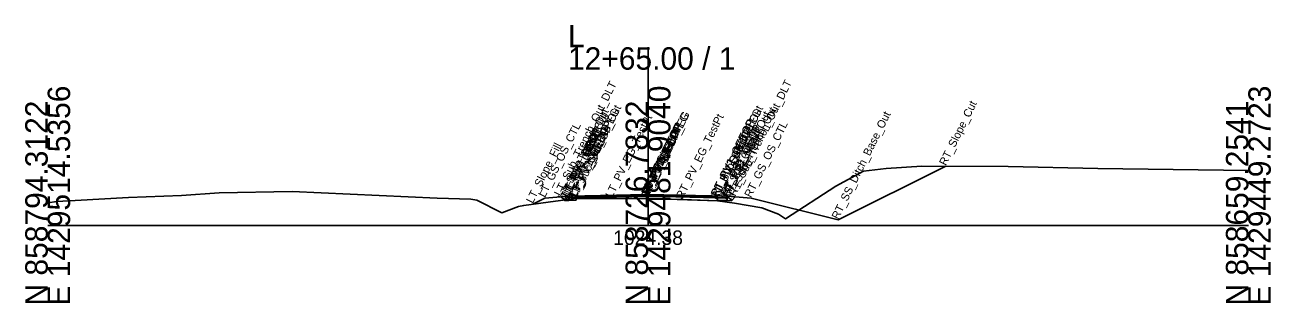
# Model space of a CAD drawing. Extents: x -26 to 2303, y -10 to 19558.
# Drawn here: x 1147.2 to 1302.8, y 3490.3 to 3525.1 of the extents above; entities that cross this region are included whole.
import ezdxf

# ---------------------------------------------------------------- set-up
doc = ezdxf.new("R2010")
doc.units = 0
for name, color, linetype in [('Default', 7, 'Continuous'), ('Exist CMT Pavement', 7, 'Continuous'), ('Exist Cross Section Cell', 7, 'Continuous'), ('Exist XS Center Line Elevation Label', 7, 'Continuous'), ('Exist XS Ground Line', 7, 'Continuous'), ('Prop CMT Conc Surface', 7, 'Continuous'), ('Prop CMT Pvmt Course 1', 7, 'Continuous'), ('Prop CMT Pvmt Course 1 Wedge', 7, 'Continuous'), ('Prop CMT Pvmt Course 2', 7, 'Continuous'), ('Prop CMT Pvmt Course 2 Wedge', 7, 'Continuous'), ('Prop CMT Pvmt Surface', 7, 'Continuous'), ('Prop CMT Pvmt Surface Shoulder', 7, 'Continuous'), ('Prop CMT Pvmt Wedge Surface 1', 7, 'Continuous'), ('Prop CMT Pvmt Wedge Surface 2', 7, 'Continuous'), ('Prop CMT Shld Paved Course 1', 7, 'Continuous'), ('Prop CMT Shld Paved Course 2', 7, 'Continuous'), ('Prop CMT Slope Grass', 7, 'Continuous'), ('Prop CMT Subgrade Earthwork', 7, 'Continuous'), ('Prop XS Dump Level', 7, 'Continuous')]:
    doc.layers.add(name, color=color, linetype=linetype)

msp = doc.modelspace()

# ---------------------------------------------------------------- linework, layer by layer
at = {"layer": 'Exist CMT Pavement'}
for p, q in [((1225, 3503.66), (1216.01, 3503.48)), ((1216.01, 3503.48), (1216.01, 3503.36)), ((1216.01, 3503.36), (1216.03, 3503.36)), ((1216.03, 3503.36), (1220.51, 3503.38)), ((1216.03, 3503.36), (1216.03, 3503.36)), ((1220.51, 3503.38), (1220.51, 3503.38)), ((1220.51, 3503.38), (1220.73, 3503.38)), ((1229.4, 3503.57), (1225, 3503.66)), ((1225, 3503.38), (1225, 3503.38)), ((1225, 3503.38), (1229.08, 3503.25)), ((1229.08, 3503.25), (1229.4, 3503.57))]:
    msp.add_line(p, q, dxfattribs=at)
for points in [[(1225, 3503.38), (1216.01, 3503.36)], [(1216.01, 3503.36), (1220.51, 3503.38)], [(1216.03, 3503.36), (1216.03, 3503.36)], [(1220.51, 3503.38), (1225, 3503.38)], [(1220.73, 3503.38), (1224.74, 3503.39), (1225, 3503.38)], [(1229.34, 3503.24), (1225, 3503.38)], [(1225, 3503.38), (1233.68, 3503.09)], [(1233.68, 3503.09), (1229.34, 3503.24)]]:
    msp.add_lwpolyline(points, dxfattribs=at)
at = {"layer": 'Exist Cross Section Cell'}
for p, q in [((1225, 3500), (1225, 3522.27)), ((1150, 3500), (1225, 3500)), ((1225, 3500), (1300, 3500))]:
    msp.add_line(p, q, dxfattribs=at)
at = {"layer": 'Exist XS Ground Line'}
msp.add_lwpolyline([(1150, 3502.84), (1151.14, 3502.98), (1153.44, 3503.13), (1160.09, 3503.48), (1166.73, 3503.74), (1171.42, 3504.07), (1180.56, 3504.23), (1198.65, 3503.42), (1202.88, 3503.28), (1203.6, 3503.16), (1206.73, 3501.58), (1208.83, 3502.36), (1209.47, 3502.52), (1213.45, 3503.06), (1216.01, 3503.36), (1220.73, 3503.38), (1224.74, 3503.39), (1229.94, 3503.22), (1233.68, 3503.09), (1235.8, 3502.78), (1239.22, 3502.21), (1241.29, 3501.4), (1242.18, 3500.85), (1248.45, 3504.9), (1251.91, 3506.81), (1254.76, 3507.14), (1259.19, 3507.42), (1269.98, 3507.37), (1281.2, 3507.13), (1300, 3506.86)], dxfattribs=at)
at = {"layer": 'Prop CMT Conc Surface'}
msp.add_line((1233.68, 3503.09), (1233.68, 3503.14), dxfattribs=at)
at = {"layer": 'Prop CMT Pvmt Course 1'}
for points in [[(1225, 3503.87), (1215.12, 3503.67)], [(1215.12, 3503.67), (1215.12, 3503.46)], [(1215.12, 3503.46), (1216.01, 3503.48)], [(1216.01, 3503.57), (1225, 3503.75)], [(1216.01, 3503.48), (1216.01, 3503.57)], [(1225, 3503.66), (1225, 3503.87)], [(1225, 3503.87), (1234.87, 3503.65)], [(1225, 3503.66), (1225, 3503.87)], [(1225, 3503.75), (1225, 3503.66), (1225, 3503.66)], [(1233.68, 3503.55), (1225, 3503.75)], [(1225, 3503.75), (1225, 3503.66), (1225, 3503.66)], [(1233.68, 3503.47), (1233.68, 3503.55)], [(1234.87, 3503.44), (1233.68, 3503.47)], [(1234.87, 3503.65), (1234.87, 3503.44)]]:
    msp.add_lwpolyline(points, dxfattribs=at)
at = {"layer": 'Prop CMT Pvmt Course 1 Wedge'}
for points in [[(1225, 3503.75), (1216.01, 3503.57)], [(1225, 3503.75), (1233.68, 3503.55)]]:
    msp.add_lwpolyline(points, dxfattribs=at)
at = {"layer": 'Prop CMT Pvmt Course 2'}
for points in [[(1216.01, 3503.48), (1215.12, 3503.46)], [(1215.12, 3503.46), (1215.12, 3503.13)], [(1215.12, 3503.13), (1216.01, 3503.15)], [(1216.01, 3503.15), (1216.01, 3503.48)], [(1233.68, 3503.14), (1233.68, 3503.47)], [(1233.68, 3503.47), (1234.87, 3503.44)], [(1234.87, 3503.11), (1233.68, 3503.14)], [(1234.87, 3503.44), (1234.87, 3503.11)]]:
    msp.add_lwpolyline(points, dxfattribs=at)
at = {"layer": 'Prop CMT Pvmt Course 2 Wedge'}
for points in [[(1225, 3503.66), (1216.01, 3503.48)], [(1225, 3503.66), (1233.68, 3503.47)]]:
    msp.add_lwpolyline(points, dxfattribs=at)
at = {"layer": 'Prop CMT Pvmt Surface'}
for points in [[(1225, 3503.87), (1215.12, 3503.67)], [(1225, 3503.87), (1234.87, 3503.65)]]:
    msp.add_lwpolyline(points, dxfattribs=at)
at = {"layer": 'Prop CMT Pvmt Surface Shoulder'}
for points in [[(1215.12, 3503.67), (1215.12, 3503.67)], [(1234.87, 3503.65), (1234.87, 3503.65)]]:
    msp.add_lwpolyline(points, dxfattribs=at)
at = {"layer": 'Prop CMT Pvmt Wedge Surface 1'}
for points in [[(1215.12, 3503.46), (1215.12, 3503.67)], [(1216.01, 3503.48), (1215.12, 3503.46)], [(1225, 3503.75), (1216.01, 3503.57)], [(1216.01, 3503.57), (1216.01, 3503.48)], [(1225, 3503.75), (1233.68, 3503.55)], [(1233.68, 3503.55), (1233.68, 3503.47)], [(1233.68, 3503.47), (1234.87, 3503.44)], [(1234.87, 3503.44), (1234.87, 3503.65)]]:
    msp.add_lwpolyline(points, dxfattribs=at)
at = {"layer": 'Prop CMT Pvmt Wedge Surface 2'}
for points in [[(1215.12, 3503.46), (1215.12, 3503.67)], [(1225, 3503.66), (1215.12, 3503.46)], [(1225, 3503.66), (1234.87, 3503.44)], [(1234.87, 3503.44), (1234.87, 3503.65)]]:
    msp.add_lwpolyline(points, dxfattribs=at)
at = {"layer": 'Prop CMT Shld Paved Course 1'}
for points in [[(1215.12, 3503.67), (1214.91, 3503.46)], [(1214.91, 3503.46), (1215.12, 3503.46)], [(1215.12, 3503.67), (1215.12, 3503.67)], [(1215.12, 3503.46), (1215.12, 3503.67)], [(1234.87, 3503.65), (1234.87, 3503.65)], [(1234.87, 3503.65), (1235.09, 3503.44)], [(1234.87, 3503.44), (1234.87, 3503.65)], [(1235.09, 3503.44), (1234.87, 3503.44)]]:
    msp.add_lwpolyline(points, dxfattribs=at)
at = {"layer": 'Prop CMT Shld Paved Course 2'}
for points in [[(1214.91, 3503.46), (1214.57, 3503.12)], [(1214.57, 3503.12), (1215.12, 3503.13)], [(1215.12, 3503.46), (1214.91, 3503.46)], [(1214.91, 3503.46), (1214.91, 3503.46)], [(1215.12, 3503.13), (1215.12, 3503.46)], [(1229.4, 3503.57), (1229.08, 3503.25)], [(1234.87, 3503.44), (1235.09, 3503.44)], [(1234.87, 3503.11), (1234.87, 3503.44)], [(1235.43, 3503.1), (1234.87, 3503.11)], [(1235.09, 3503.44), (1235.09, 3503.44)], [(1235.09, 3503.44), (1235.43, 3503.1)]]:
    msp.add_lwpolyline(points, dxfattribs=at)
at = {"layer": 'Prop CMT Slope Grass'}
for points in [[(1234.87, 3503.65), (1237.87, 3503.41), (1248.77, 3500.69), (1262.21, 3507.41)], [(1215.12, 3503.67), (1212.12, 3503.43), (1210.61, 3502.68)]]:
    msp.add_lwpolyline(points, dxfattribs=at)
at = {"layer": 'Prop CMT Subgrade Earthwork'}
for points in [[(1214.57, 3503.12), (1214.1, 3503.59)], [(1215.12, 3503.13), (1214.57, 3503.12)], [(1216.01, 3503.15), (1215.12, 3503.13)], [(1216.01, 3503.15), (1216.03, 3503.36)], [(1233.68, 3503.14), (1233.66, 3503.09)], [(1233.68, 3503.14), (1234.87, 3503.11)], [(1234.87, 3503.11), (1235.43, 3503.1)], [(1235.43, 3503.1), (1235.9, 3503.57)]]:
    msp.add_lwpolyline(points, dxfattribs=at)

# ---------------------------------------------------------------- texts
at = {"layer": 'Default'}
msp.add_text('-', height=0.0001, dxfattribs=at).set_placement((1150, 3500))
at = {"layer": 'Exist Cross Section Cell'}
for s, p in [('L', (1215, 3522.27)), ('12+65.00 / 1', (1215, 3519.47))]:
    msp.add_text(s, height=2.8, dxfattribs=at).set_placement(p)
for s, p in [('E 1429514.5356', (1152.8, 3490)), ('E 1429481.9040', (1227.8, 3490)), ('E 1429449.2723', (1302.8, 3490)), ('N 858794.3122', (1150, 3490)), ('N 858726.7832', (1225, 3490)), ('N 858659.2541', (1300, 3490))]:
    msp.add_text(s, height=2.8, rotation=90, dxfattribs=at).set_placement(p)
at = {"layer": 'Exist XS Center Line Elevation Label'}
msp.add_text('1024.38', height=1.8, dxfattribs=at).set_placement((1220.66, 3497.58))
at = {"layer": 'Prop XS Dump Level'}
for s, p in [('LT_Sub_Trench_Out_DLT', (1214.1, 3503.59)), ('RT_Sub_Trench_Out_DLT', (1235.9, 3503.57)), ('RT_Slope_Cut', (1262.21, 3507.41)), ('LT_Sub_Trench_Out', (1214.57, 3503.12)), ('LT_PS2_Shelf_Out', (1214.91, 3503.46)), ('LT_PV_OEEOP_EG', (1216.01, 3503.36)), ('LT_PV_Sub_Tie_Out', (1216.03, 3503.36)), ('LT_PV_EG_TestPt', (1220.51, 3503.38)), ('RT_PV_IEEOP_EG', (1225, 3503.38)), ('LT_PV_IEEOP_EG', (1225, 3503.38)), ('RT_PV_EG_TestPt', (1229.34, 3503.24)), ('RT_PV_Sub_Tie_Out', (1233.66, 3503.09)), ('RT_PV_OEEOP_EG', (1233.68, 3503.09)), ('RT_PS2_Shelf_Out', (1235.09, 3503.44)), ('RT_Sub_Trench_Out', (1235.43, 3503.1)), ('RT_SS_Ditch_Base_Out', (1248.77, 3500.69)), ('LT_GS_OS_CTL', (1212.12, 3503.43)), ('LT_PS2_OEOP', (1214.91, 3503.46)), ('LT_PV1_OEOT', (1215.12, 3503.67)), ('LT_PS1_OEOP', (1215.12, 3503.67)), ('LT_PV2_OEOT', (1215.12, 3503.46)), ('LT_PV1_OEEOP', (1216.01, 3503.57)), ('LT_PV2_OEEOP', (1216.01, 3503.48)), ('LT_Sub_OEEOP', (1216.01, 3503.15)), ('RT_PV1_IEEOP', (1225, 3503.75)), ('RT_PV2_IEEOP', (1225, 3503.66)), ('LT_PV1_IEEOP', (1225, 3503.75)), ('LT_PV2_IEEOP', (1225, 3503.66)), ('RT_PV1_OEEOP', (1233.68, 3503.55)), ('RT_PV2_OEEOP', (1233.68, 3503.47)), ('RT_Sub_OEEOP', (1233.68, 3503.14)), ('RT_PV1_OEOT', (1234.87, 3503.65)), ('RT_PS1_OEOP', (1234.87, 3503.65)), ('RT_PV2_OEOT', (1234.87, 3503.44)), ('RT_PS2_OEOP', (1235.09, 3503.44)), ('RT_GS_OS_CTL', (1237.87, 3503.41)), ('LT_Sub_OEOT', (1215.12, 3503.13)), ('RT_Sub_OEOT', (1234.87, 3503.11)), ('LT_Slope_Fill', (1210.61, 3502.68)), ('PV1_PGL', (1225, 3503.87)), ('PV2_PGL', (1225, 3503.66))]:
    msp.add_text(s, height=1, rotation=63.5833, dxfattribs=at).set_placement(p)

doc.saveas('drawing.dxf')
